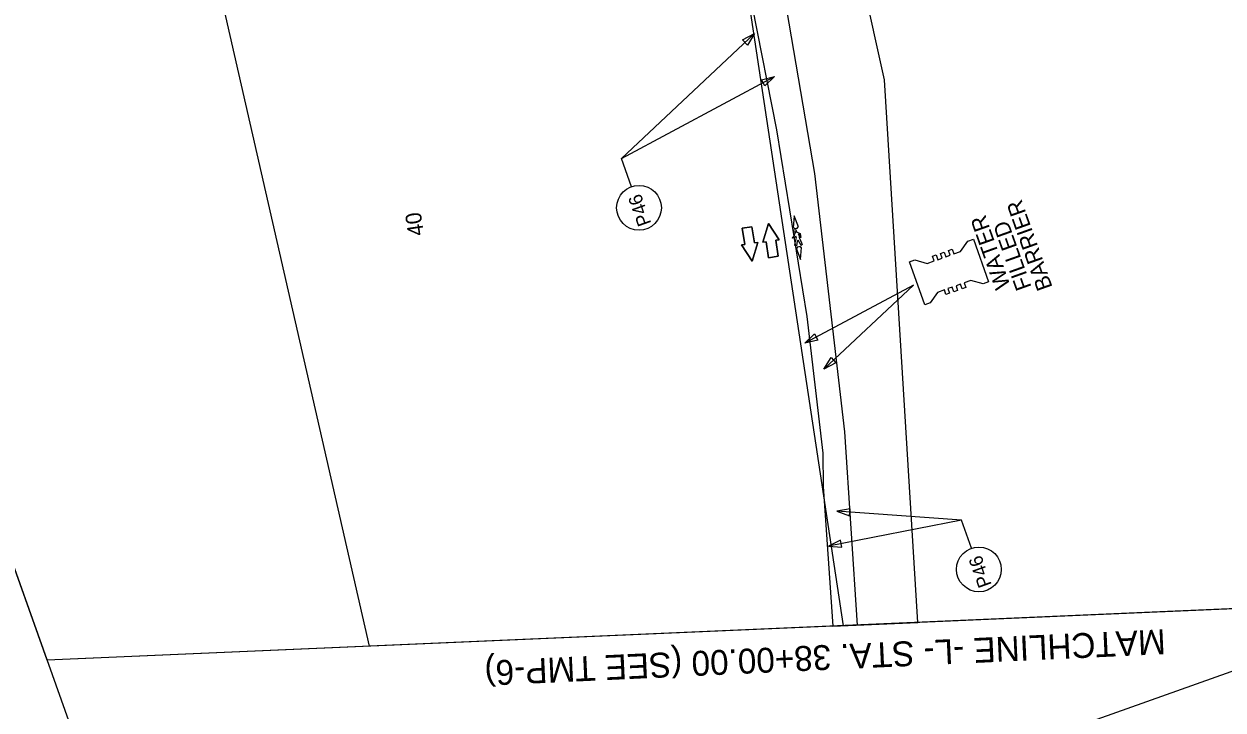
# Model space of a CAD drawing. Extents: x 1615843 to 1618439, y 899470 to 903922.
# Drawn here: x 1616337 to 1616867, y 902336 to 902639 of the extents above; entities that cross this region are included whole.
import ezdxf

# ---------------------------------------------------------------- set-up
doc = ezdxf.new("R2010")
doc.units = 0
for name, color, linetype in [('Default', 7, 'Continuous'), ('DEV DIRECTION OF TRAFFIC FLOW ARROW CELL', 7, 'Continuous'), ('DEV WATER FILLED BARRIER CELL', 7, 'Continuous'), ('Matchline', 7, 'Continuous'), ('Matchline Text', 7, 'Continuous'), ('Prop Horizontal Alignment Tick Label', 7, 'Continuous'), ('Scratch_Level_0', 7, 'Continuous'), ('Scratch_Level_5', 7, 'Continuous'), ('Sheet Clip Boundary CELL', 7, 'Continuous')]:
    doc.layers.add(name, color=color, linetype=linetype)

msp = doc.modelspace()

# ---------------------------------------------------------------- linework, layer by layer
at = {"layer": 'Default'}
for p, q in [((1616601.21, 902579.72), (1616668.87, 902615.91)), ((1616730.24, 902523.88), (1616682.14, 902498.15)), ((1616730.24, 902523.88), (1616690.66, 902486.69)), ((1616751.36, 902419.99), (1616692.6, 902408.57))]:
    msp.add_line(p, q, dxfattribs=at)
for points in [[(1616605.62, 902567.3), (1616601.21, 902579.72), (1616659.98, 902634.95)], [(1616755.77, 902407.58), (1616751.36, 902419.99), (1616696.28, 902423.92)]]:
    msp.add_lwpolyline(points, dxfattribs=at)
for points in [[(1616654.7, 902632.11), (1616659.98, 902634.95), (1616656.82, 902629.85)], [(1616663.02, 902614.55), (1616668.87, 902615.91), (1616664.49, 902611.81)], [(1616687.98, 902499.51), (1616682.14, 902498.15), (1616686.52, 902502.25)], [(1616695.95, 902489.52), (1616690.66, 902486.69), (1616693.82, 902491.79)], [(1616702.17, 902425.06), (1616696.28, 902423.92), (1616701.95, 902421.96)], [(1616697.99, 902411.2), (1616692.6, 902408.57), (1616698.58, 902408.15)]]:
    msp.add_lwpolyline(points, close=True, dxfattribs=at)
for centre in [(1616608.94, 902557.98), (1616759.09, 902398.25)]:
    msp.add_circle(centre, 9.89, dxfattribs=at)
at = {"layer": 'DEV DIRECTION OF TRAFFIC FLOW ARROW CELL'}
for p, q in [((1616677.48, 902554.46), (1616677.03, 902549.17)), ((1616679.44, 902549.53), (1616677.48, 902554.46)), ((1616658.85, 902549.58), (1616654.55, 902548.93)), ((1616654.55, 902548.93), (1616658.85, 902549.58)), ((1616654.55, 902548.93), (1616655.63, 902541.81)), ((1616655.63, 902541.81), (1616654.55, 902548.93)), ((1616659.92, 902542.46), (1616658.85, 902549.58)), ((1616658.85, 902549.58), (1616659.92, 902542.46)), ((1616666.1, 902551.01), (1616663.64, 902542.8)), ((1616663.64, 902542.8), (1616666.1, 902551.01)), ((1616670.87, 902543.89), (1616666.1, 902551.01)), ((1616666.1, 902551.01), (1616670.87, 902543.89)), ((1616677.03, 902549.17), (1616677.52, 902549.25)), ((1616677.52, 902549.25), (1616677.59, 902548.78)), ((1616677.59, 902548.78), (1616679.02, 902548.99)), ((1616678.86, 902547.18), (1616680.21, 902546.62)), ((1616678.95, 902549.45), (1616679.44, 902549.53)), ((1616679.02, 902548.99), (1616678.95, 902549.45)), ((1616655.63, 902541.81), (1616654.16, 902541.59)), ((1616654.16, 902541.59), (1616655.63, 902541.81)), ((1616658.93, 902534.47), (1616661.39, 902542.68)), ((1616661.39, 902542.68), (1616658.93, 902534.47)), ((1616661.39, 902542.68), (1616659.92, 902542.46)), ((1616659.92, 902542.46), (1616661.39, 902542.68)), ((1616663.64, 902542.8), (1616665.11, 902543.02)), ((1616665.11, 902543.02), (1616663.64, 902542.8)), ((1616665.11, 902543.02), (1616666.18, 902535.9)), ((1616666.18, 902535.9), (1616665.11, 902543.02)), ((1616669.4, 902543.67), (1616670.87, 902543.89)), ((1616670.87, 902543.89), (1616669.4, 902543.67)), ((1616670.48, 902536.55), (1616669.4, 902543.67)), ((1616669.4, 902543.67), (1616670.48, 902536.55)), ((1616676.55, 902544.74), (1616677.66, 902545.73)), ((1616676.79, 902544.5), (1616676.55, 902544.74)), ((1616677.86, 902545.04), (1616676.79, 902544.5)), ((1616677.66, 902545.73), (1616677.67, 902546.23)), ((1616677.82, 902541.26), (1616678.05, 902543.34)), ((1616678.19, 902545.45), (1616677.86, 902545.04)), ((1616678.05, 902543.34), (1616678.5, 902544.55)), ((1616678.8, 902543.17), (1616678.51, 902541.15)), ((1616679.21, 902543.73), (1616678.8, 902543.17)), ((1616680.57, 902541.31), (1616679.21, 902543.73)), ((1616679.8, 902546.24), (1616679.39, 902546.26)), ((1616680.12, 902544.86), (1616679.8, 902546.24)), ((1616679.97, 902544.29), (1616681, 902541.71)), ((1616680.48, 902544.91), (1616680.12, 902544.86)), ((1616680.21, 902546.62), (1616680.48, 902544.91)), ((1616681, 902541.71), (1616680.57, 902541.31)), ((1616654.16, 902541.59), (1616658.93, 902534.47)), ((1616658.93, 902534.47), (1616654.16, 902541.59)), ((1616666.18, 902535.9), (1616670.48, 902536.55)), ((1616670.48, 902536.55), (1616666.18, 902535.9)), ((1616678.51, 902541.15), (1616677.82, 902541.26)), ((1616678.86, 902540.18), (1616678.37, 902540.11)), ((1616678.37, 902540.11), (1616680.33, 902535.17)), ((1616680.22, 902540.85), (1616678.79, 902540.64)), ((1616678.79, 902540.64), (1616678.86, 902540.18)), ((1616680.29, 902540.39), (1616680.22, 902540.85)), ((1616680.78, 902540.46), (1616680.29, 902540.39)), ((1616680.33, 902535.17), (1616680.78, 902540.46))]:
    msp.add_line(p, q, dxfattribs=at)
msp.add_circle((1616677.79, 902547.82), 0.555, dxfattribs=at)
for centre, radius, start, end in [((1616679.28, 902546.2), 1.61, 148.5663, 178.9541), ((1616678.27, 902546.82), 0.42, 105.2791, 148.5663), ((1616678.45, 902546.17), 1.09, 67.5443, 105.2791), ((1616675.82, 902544.15), 2.7, 8.6865, 28.7657), ((1616675.82, 902544.15), 4.15, 2.0341, 30.6324)]:
    msp.add_arc(centre, radius, start, end, dxfattribs=at)
at = {"layer": 'DEV WATER FILLED BARRIER CELL'}
msp.add_lwpolyline([(1616735.15, 902515.16), (1616728.42, 902534.09), (1616730.86, 902534.96), (1616736.27, 902533.42), (1616739.29, 902534.5), (1616738.55, 902536.57), (1616740.17, 902537.14), (1616740.91, 902535.07), (1616742.83, 902535.75), (1616742.09, 902537.82), (1616743.71, 902538.4), (1616744.45, 902536.33), (1616746.37, 902537.02), (1616745.64, 902539.08), (1616747.26, 902539.66), (1616748, 902537.59), (1616751.01, 902538.66), (1616754.25, 902543.27), (1616756.68, 902544.14), (1616763.41, 902525.21), (1616760.98, 902524.34), (1616755.56, 902525.87), (1616752.54, 902524.8), (1616753.28, 902522.73), (1616751.66, 902522.16), (1616750.92, 902524.22), (1616749, 902523.54), (1616749.73, 902521.47), (1616748.11, 902520.9), (1616747.37, 902522.96), (1616745.45, 902522.28), (1616746.19, 902520.21), (1616744.57, 902519.64), (1616743.84, 902521.7), (1616740.82, 902520.63), (1616737.59, 902516.03)], close=True, dxfattribs=at)
msp.add_lwpolyline([(1616735.15, 902515.16), (1616728.42, 902534.09), (1616730.86, 902534.96), (1616736.27, 902533.42), (1616739.29, 902534.5), (1616738.55, 902536.57), (1616740.17, 902537.14), (1616740.91, 902535.07), (1616742.83, 902535.75), (1616742.09, 902537.82), (1616743.71, 902538.4), (1616744.45, 902536.33), (1616746.37, 902537.02), (1616745.64, 902539.08), (1616747.26, 902539.66), (1616748, 902537.59), (1616751.01, 902538.66), (1616754.25, 902543.27), (1616756.68, 902544.14), (1616763.41, 902525.21), (1616760.98, 902524.34), (1616755.56, 902525.87), (1616752.54, 902524.8), (1616753.28, 902522.73), (1616751.66, 902522.16), (1616750.92, 902524.22), (1616749, 902523.54), (1616749.73, 902521.47), (1616748.11, 902520.9), (1616747.37, 902522.96), (1616745.45, 902522.28), (1616746.19, 902520.21), (1616744.57, 902519.64), (1616743.84, 902521.7), (1616740.82, 902520.63), (1616737.59, 902516.03)], close=True, dxfattribs=at)
at = {"layer": 'Matchline'}
msp.add_line((1616959.09, 902384.66), (1616347.43, 902358.15), dxfattribs=at)
at = {"layer": 'Scratch_Level_0'}
msp.add_lwpolyline([(1615938.73, 903507.75), (1616407.69, 902188.63), (1617302.81, 902506.85), (1617008.42, 903334.93), (1616896.98, 903295.32), (1616722.42, 903786.36)], close=True, dxfattribs=at)
at = {"layer": 'Scratch_Level_5'}
for points in [[(1616347.43, 902358.15), (1615993.9, 903352.57), (1616755.41, 903693.55), (1617118.27, 903131.4), (1617302.81, 902506.85), (1616959.09, 902384.66)], [(1616705.54, 902373.67), (1616699.85, 902458.96), (1616686.62, 902573.2), (1616667.04, 902687.93), (1616638.01, 902809.43), (1616596.83, 902943.32), (1616588.98, 902949.04), (1616499.35, 903201.92), (1616504.06, 903203.6), (1616506.92, 903204.49), (1616400, 903496.37), (1616388.07, 903529.07), (1616755.41, 903693.55), (1617118.27, 903131.4), (1617302.81, 902506.85), (1616959.09, 902384.66)], [(1616699.32, 902373.4), (1616633.77, 902806.46), (1616631.94, 902813.22), (1616597.93, 902897.46), (1616599.33, 902920.4), (1616597.1, 902927.03), (1616370.6, 903502.2), (1616643.52, 903550.34), (1617118.27, 903131.4), (1617302.81, 902506.85), (1616959.09, 902384.66)]]:
    msp.add_lwpolyline(points, close=True, dxfattribs=at)
at = {"layer": 'Sheet Clip Boundary CELL'}
for points in [[(1616920.55, 902382.99), (1616489.91, 902364.33), (1616361.78, 902925.96), (1616113.49, 903406.12), (1616903.33, 903759.78), (1617118.27, 903131.4), (1617236.29, 902693.96), (1617083.45, 902390.05)], [(1616694.55, 902373.19), (1616732.15, 902374.79), (1616717.45, 902614.43), (1616639.68, 902965.04), (1616763.33, 903001.21), (1616761.22, 903018.27), (1616752.73, 903054.64), (1616632.71, 903026.28), (1616564.32, 903130.19), (1616414.61, 903540.98), (1616374.17, 903522.92), (1616456.37, 903298.56), (1616566.89, 902980.98), (1616598.23, 902894.85), (1616630.48, 902783.84), (1616648.21, 902701.52), (1616669.68, 902592.43), (1616683.11, 902510.03), (1616690.19, 902449.56), (1616690.27, 902434.92)]]:
    msp.add_lwpolyline(points, close=True, dxfattribs=at)

# ---------------------------------------------------------------- texts
at = {"layer": 'Default'}
for s, height, rotation, p in [('P46', 6, 109.5707, (1616614.41, 902551.11)), ('BARRIER', 7, 109.5708, (1616791.74, 902522.91)), ('WATER ', 7, 109.5708, (1616773.16, 902523.48)), ('FILLED', 7, 109.5708, (1616782.44, 902522.97)), ('P46', 6, 109.5706, (1616764.84, 902391.48))]:
    msp.add_text(s, height=height, rotation=rotation, dxfattribs=at).set_placement(p)
at = {"layer": 'Matchline Text'}
msp.add_text('MATCHLINE -L- STA. 38+00.00 (SEE TMP-6)', height=11, rotation=182.6625, dxfattribs=at).set_placement((1616841.36, 902371.86))
at = {"layer": 'Prop Horizontal Alignment Tick Label'}
msp.add_text('40', height=7, rotation=98.273, dxfattribs=at).set_placement((1616513.95, 902546.08))

doc.saveas('drawing.dxf')
